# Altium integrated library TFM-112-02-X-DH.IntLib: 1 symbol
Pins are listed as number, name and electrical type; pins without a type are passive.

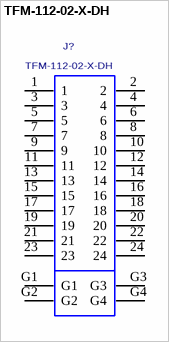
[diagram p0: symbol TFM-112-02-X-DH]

## TFM-112-02-X-DH
designator J?
0.050" DOUBLE HORIZONTAL TERMINAL STRIP.; MANUFACTURER: SAMTEC
footprint TFM-112-02-X-DH
pins: 1, 2, 3, 4, 5, 6, 7, 8, 9, 10, 11, 12, 13, 14, 15, 16, 17, 18, 19, 20, 21, 22, 23, 24, G1, G2, G3, G4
